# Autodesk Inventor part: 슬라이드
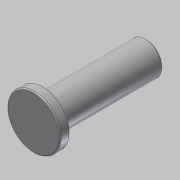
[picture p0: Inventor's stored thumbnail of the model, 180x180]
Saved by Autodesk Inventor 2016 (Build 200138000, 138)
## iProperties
Company: 한국ATC센터
Created: 2015-11
Part Number: 슬라이드
Document SubType Name: Modeling
Designer: mdu
Density: 7.86 g/cm^3
Material: 강철, 연강
Mass: 53.0481 g
Surface Area: 25.6984 cm^2
Volume: 6.74912 cm^3
Appearance: 강철
Author: mdu
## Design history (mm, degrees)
sketch "스케치1"
  geometry: L1 (13.5, 41)-(13.5, 74) reference; L2 (13.5, 74)-(26.5, 74) reference; L3 (20, 74)-(20, 29); L4 (20, 74)-(13.5, 74); L5 (13.5, 74)-(13.5, 33); L6 (13.5, 33)-(9.5, 33); L7 (9.5, 33)-(9.5, 29); L8 (20, 73.5)-(13.5, 73.5); L9 (20, 29)-(9.5, 29); 1 further point
  constraints: 16 end point, 4 perpendicular, 3 point on line, 1 collinear, 1 midpoint, 1 parallel, 1 vertical, 2 other
  dimensions: "d0" = 45 distance of L3.start L3.end; "d1" = 21 diameter of L7 L3; "d2" = 4 distance from line of L3.end L6; "d4" = 0.5 distance between parallel lines of L8 L2
revolve "회전1" sketch "스케치1" stored, may be unused: angle "d5" = 90 deg
fillet "모깎기1" dims "d6" = 0.5
chamfer "모따기1" distance "d9" = 0.5; stored, may be unused: second distance "d10" = 2, angle "d11" = 45 deg
node "솔리드1"
node "참조1"
